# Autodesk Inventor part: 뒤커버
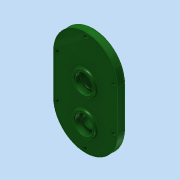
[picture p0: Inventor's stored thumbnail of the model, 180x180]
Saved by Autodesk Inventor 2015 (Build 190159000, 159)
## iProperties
Created: 2016-12
Part Number: 뒤커버
Material: 알루미늄 6061
Document SubType Name: Modeling
Designer: mduedu
Density: 2.71 g/cm^3
Appearance: 매끄러움 - 짙은 산림 녹색
Mass: 236.334 g
Surface Area: 240.959 cm^2
Volume: 87.2081 cm^3
Author: mduedu
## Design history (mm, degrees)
sketch "스케치1"
  geometry: L1 (40, -25)-(40, 25); L2 (-40, 25)-(-40, -25); L3 (-40, -25)-(40, 25); L4 (40, -25)-(-40, 25); A1 r 40 centre (0, 25) between (40, 25) and (-40, 25); A2 r 40 centre (0, -25) between (-40, -25) and (40, -25); 1 further point
  constraints: 8 end point, 4 point on circle, 4 tangent, 2 centre point, 2 midpoint, 1 parallel, 1 vertical
  dimensions: "d0" = 130 dimension on A2 A1; "d2" = 80 distance between parallel lines of L1 L2
extrude "돌출1" new body sketch "스케치1" distance "d3" = 10; taper "d4" = 0 deg
sketch "스케치2"
  geometry: C1 r 14 at (0, 11); 1 further point
  constraints: 1 centre point, 1 vertical alignment
  dimensions: "d5" = 28 diameter of C1; "d6" = 11 distance of C1.centre point (0, 0)
extrude "돌출2" join sketch "스케치2" distance "d7" = 3; taper "d8" = 0 deg
sketch "스케치3"
  geometry: C1 r 14 at (0, -33.1); C2 r 14 at (0, 11) reference; 1 further point
  constraints: 1 centre point, 1 vertical alignment
  dimensions: "d9" = 28 diameter of C1; "d69" = 44.1 distance of C1.centre C2.centre
extrude "돌출3" join sketch "스케치3" distance "d11" = 3; taper "d12" = 0 deg
hole "구멍1" diameter "d15" = 22; stored, may be unused: countersink angle "d19" = 90 deg, drill point angle "d21" = 0 deg; dims "d13" = 10, "d14" = 10, "d16" = 6, "d17" = 4, "d18" = 2, "d20" = 7
hole "구멍2" diameter "d24" = 18; stored, may be unused: countersink angle "d28" = 90 deg, drill point angle "d30" = 0 deg; dims "d22" = 10, "d23" = 10, "d25" = 6, "d26" = 4, "d27" = 2, "d29" = 1
hole "구멍3" diameter "d33" = 22; stored, may be unused: countersink angle "d37" = 90 deg, drill point angle "d39" = 0 deg; dims "d31" = 10, "d32" = 10, "d34" = 6, "d35" = 4, "d36" = 2, "d38" = 7
sketch "스케치4"
  geometry: C1 r 14 at (0, -33.1) reference; C2 r 18 at (0, -33.1); 1 further point
  constraints: 1 centre point, 1 coincident
  dimensions: "d40" = 36 diameter of C2
extrude "돌출4" join sketch "스케치4" distance "d41" = 4; taper "d42" = 0 deg
hole "구멍4" diameter "d45" = 22; stored, may be unused: countersink angle "d49" = 90 deg, drill point angle "d51" = 0 deg; dims "d46" = 6, "d47" = 4, "d48" = 2, "d50" = 7.3, "d80" = 10, "d81" = 10
hole "구멍5" diameter "d54" = 15; stored, may be unused: countersink angle "d58" = 90 deg, drill point angle "d60" = 0 deg; dims "d52" = 10, "d53" = 10, "d55" = 6, "d56" = 4, "d57" = 2, "d59" = 7
fillet "모깎기1" dims "d61" = 0.3
fillet "모깎기2" dims "d62" = 2
chamfer "모따기1" distance "d63" = 1; stored, may be unused: second distance "d64" = 2, angle "d65" = 45 deg
chamfer "모따기2" distance "d82" = 0.7; stored, may be unused: second distance "d83" = 2, angle "d84" = 30 deg
fillet "모깎기3" dims "d66" = 2
fillet "모깎기4" dims "d67" = 2
fillet "모깎기5" dims "d68" = 2
sketch "스케치5"
  geometry: L1 (-40, 25)-(-40, -25) reference; L2 (40, -25)-(40, 25) reference; L3 (35, 25)-(35, -25); L4 (-35, -25)-(-35, 25); A1 r 40 centre (0, 25) between (40, 25) and (-40, 25) reference; A2 r 40 centre (0, -25) between (-40, -25) and (40, -25) reference; A3 r 35 centre (0, 25) between (35, 25) and (-35, 25); A4 r 35 centre (0, -25) between (-35, -25) and (35, -25); 2 further points
  constraints: 5 point on circle, 4 end point, 2 centre point, 1 vertical alignment, 3 other
  dimensions: "d70" = 5 distance between parallel lines of L2 L3
sketch "스케치6"
  geometry: 1 further point
  constraints: 1 other
hole "구멍6" sketch "스케치6" at (0, 60) diameter "d71" = 4.5; stored, may be unused: countersink angle "d75" = 90 deg, drill point angle "d77" = 0 deg; dims "d72" = 6, "d73" = 8, "d74" = 4.6, "d76" = 8
node "솔리드1"
pattern_linear "직사각형 패턴1"
